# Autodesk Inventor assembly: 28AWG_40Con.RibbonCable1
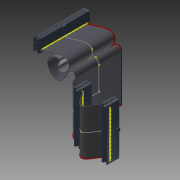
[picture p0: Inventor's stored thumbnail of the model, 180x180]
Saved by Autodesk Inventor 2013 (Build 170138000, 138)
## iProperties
ParentFileIdentifier: 5|1|0|0|168|2|0|0|80|0|65|0|84|0|72|0|83|0|59|0|67|0|58|0|92|0|80|0|114|0|111|0|103|0|114|0|97|0|109|0|32|0|70|0|105|0|108|0|101|0|115|0|92|0|65|0|117|0|116|0|1
Part Number: 28AWG_40Con.RibbonCable1
Material: Default
Description: 28AWG_40Con
Density: 1 g/cm^3
Created: 2007-02
Part Number: HD Ribbon Cable
Document SubType Name: Assembly
Designer: floress
Mass: 12.1553 g
Surface Area: 105.882 cm^2
Volume: 12.1553 cm^3
HarnessSettings: <HarnessSettings><Defaults><Segments><Diameter value="0.200 in" fromwires="True"/><Offset value="0.100 in"/><ColorStyle value="Blue"/><BendRadius value="5" from
CableDummyParamRefKey: Key:16|2|0|0|16|0|0|0|167|0|0|0|0|0|0|0|129|0|0|0|0|0|0|0|Level:1
Author: floress
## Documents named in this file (3)
- Z:\_DATEN\Personal Computer\Aip\HD Ribbon Cable.iam
- Z:\_DATEN\Personal Computer\Aip\HD Ribbon Cable.ipt
- Z:\_DATEN\Personal Computer\Aip\Ribbon Cable Connector.ipt
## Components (5 placed, 3 different names)
1. Ribbon Cable Connector:1
2. Ribbon Cable Connector:2
3. Ribbon Cable Connector:3
4. HD Ribbon Cable
5. HA_VC_100:1
